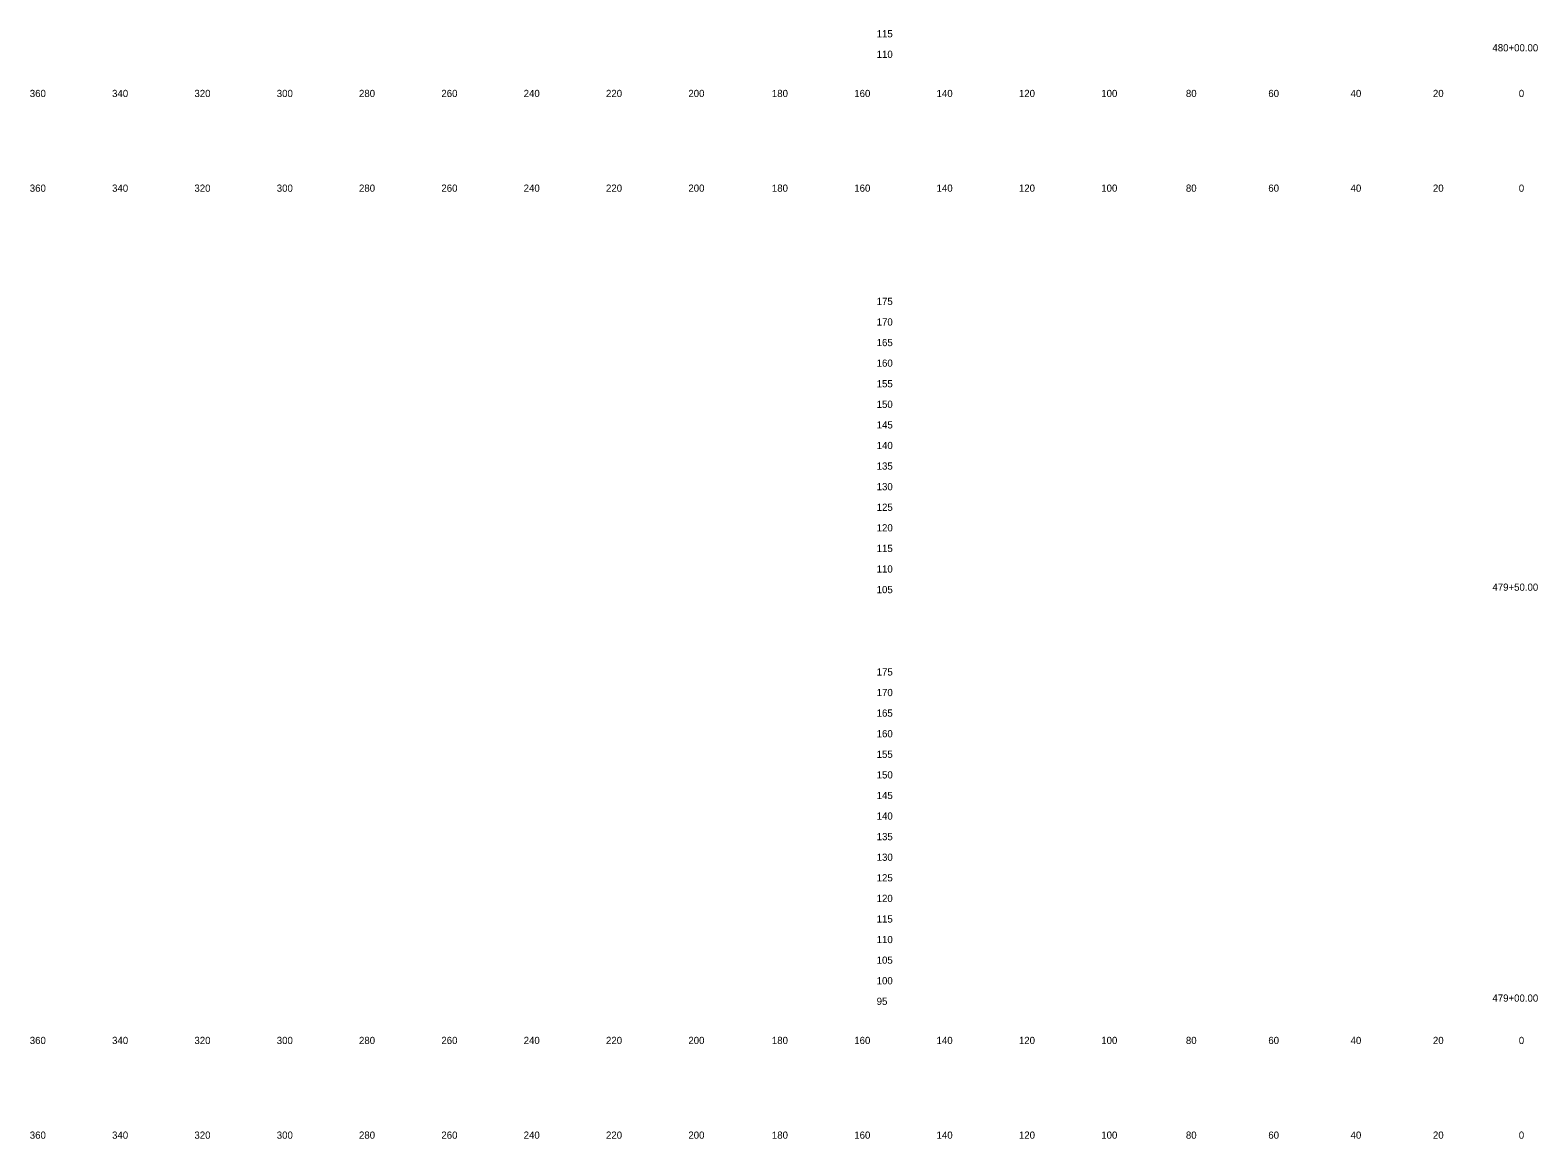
# Model space of a CAD drawing. Extents: x 21281 to 22024, y 6472 to 15198.
# Drawn here: x 21280.5 to 21646.7, y 12202.3 to 12471.6 of the extents above; entities that cross this region are included whole.
import ezdxf

# ---------------------------------------------------------------- set-up
doc = ezdxf.new("R2010")
doc.units = 0
for name, color, linetype in [('Draft_XS_Grid', 7, 'Continuous'), ('Draft_XS_Text', 7, 'Continuous'), ('SLOPE_STAKES_FILL', 7, 'Continuous')]:
    doc.layers.add(name, color=color, linetype=linetype)

msp = doc.modelspace()

# ---------------------------------------------------------------- texts
at = {"layer": 'Draft_XS_Grid'}
for s, p in [('  115  ', (21484.84, 12469.84)), ('  110  ', (21484.84, 12464.84)), ('  175  ', (21484.84, 12404.84)), ('  170  ', (21484.84, 12399.84)), ('  165  ', (21484.84, 12394.84)), ('  160  ', (21484.84, 12389.84)), ('  155  ', (21484.84, 12384.84)), ('  150  ', (21484.84, 12379.84)), ('  145  ', (21484.84, 12374.84)), ('  140  ', (21484.84, 12369.84)), ('  135  ', (21484.84, 12364.84)), ('  130  ', (21484.84, 12359.84)), ('  125  ', (21484.84, 12354.84)), ('  120  ', (21484.84, 12349.84)), ('  115  ', (21484.84, 12344.84)), ('  110  ', (21484.84, 12339.84)), ('  105  ', (21484.84, 12334.84)), ('  175  ', (21484.84, 12314.84)), ('  170  ', (21484.84, 12309.84)), ('  165  ', (21484.84, 12304.84)), ('  160  ', (21484.84, 12299.84)), ('  155  ', (21484.84, 12294.84)), ('  150  ', (21484.84, 12289.84)), ('  145  ', (21484.84, 12284.84)), ('  140  ', (21484.84, 12279.84)), ('  135  ', (21484.84, 12274.84)), ('  130  ', (21484.84, 12269.84)), ('  125  ', (21484.84, 12264.84)), ('  120  ', (21484.84, 12259.84)), ('  115  ', (21484.84, 12254.84)), ('  110  ', (21484.84, 12249.84)), ('  105  ', (21484.84, 12244.84)), ('  100  ', (21484.84, 12239.84)), ('  95  ', (21484.84, 12234.84))]:
    msp.add_text(s, height=1.75, dxfattribs=at).set_placement(p)
at = {"layer": 'Draft_XS_Text'}
for s, p in [('  360  ', (21279.14, 12455.34)), ('  340  ', (21299.13, 12455.34)), ('  320  ', (21319.13, 12455.34)), ('  300  ', (21339.13, 12455.34)), ('  280  ', (21359.1, 12455.34)), ('  260  ', (21379.11, 12455.34)), ('  240  ', (21399.1, 12455.34)), ('  220  ', (21419.1, 12455.34)), ('  200  ', (21439.1, 12455.34)), ('  180  ', (21459.39, 12455.34)), ('  160  ', (21479.4, 12455.34)), ('  140  ', (21499.39, 12455.34)), ('  120  ', (21519.39, 12455.34)), ('  100  ', (21539.39, 12455.34)), ('  80  ', (21559.95, 12455.34)), ('  60  ', (21579.97, 12455.34)), ('  40  ', (21599.95, 12455.34)), ('  20  ', (21619.95, 12455.34)), ('  0  ', (21640.81, 12455.34)), ('  0  ', (21640.81, 12455.34)), ('  360  ', (21279.14, 12432.34)), ('  340  ', (21299.13, 12432.34)), ('  320  ', (21319.13, 12432.34)), ('  300  ', (21339.13, 12432.34)), ('  280  ', (21359.1, 12432.34)), ('  260  ', (21379.11, 12432.34)), ('  240  ', (21399.1, 12432.34)), ('  220  ', (21419.1, 12432.34)), ('  200  ', (21439.1, 12432.34)), ('  180  ', (21459.39, 12432.34)), ('  160  ', (21479.4, 12432.34)), ('  140  ', (21499.39, 12432.34)), ('  120  ', (21519.39, 12432.34)), ('  100  ', (21539.39, 12432.34)), ('  80  ', (21559.95, 12432.34)), ('  60  ', (21579.97, 12432.34)), ('  40  ', (21599.95, 12432.34)), ('  20  ', (21619.95, 12432.34)), ('  0  ', (21640.81, 12432.34)), ('  0  ', (21640.81, 12432.34)), ('  360  ', (21279.14, 12225.34)), ('  340  ', (21299.13, 12225.34)), ('  320  ', (21319.13, 12225.34)), ('  300  ', (21339.13, 12225.34)), ('  280  ', (21359.1, 12225.34)), ('  260  ', (21379.11, 12225.34)), ('  240  ', (21399.1, 12225.34)), ('  220  ', (21419.1, 12225.34)), ('  200  ', (21439.1, 12225.34)), ('  180  ', (21459.39, 12225.34)), ('  160  ', (21479.4, 12225.34)), ('  140  ', (21499.39, 12225.34)), ('  120  ', (21519.39, 12225.34)), ('  100  ', (21539.39, 12225.34)), ('  80  ', (21559.95, 12225.34)), ('  60  ', (21579.97, 12225.34)), ('  40  ', (21599.95, 12225.34)), ('  20  ', (21619.95, 12225.34)), ('  0  ', (21640.81, 12225.34)), ('  0  ', (21640.81, 12225.34)), ('  360  ', (21279.14, 12202.34)), ('  340  ', (21299.13, 12202.34)), ('  320  ', (21319.13, 12202.34)), ('  300  ', (21339.13, 12202.34)), ('  280  ', (21359.1, 12202.34)), ('  260  ', (21379.11, 12202.34)), ('  240  ', (21399.1, 12202.34)), ('  220  ', (21419.1, 12202.34)), ('  200  ', (21439.1, 12202.34)), ('  180  ', (21459.39, 12202.34)), ('  160  ', (21479.4, 12202.34)), ('  140  ', (21499.39, 12202.34)), ('  120  ', (21519.39, 12202.34)), ('  100  ', (21539.39, 12202.34)), ('  80  ', (21559.95, 12202.34)), ('  60  ', (21579.97, 12202.34)), ('  40  ', (21599.95, 12202.34)), ('  20  ', (21619.95, 12202.34)), ('  0  ', (21640.81, 12202.34)), ('  0  ', (21640.81, 12202.34))]:
    msp.add_text(s, height=1.75, dxfattribs=at).set_placement(p)
at = {"layer": 'SLOPE_STAKES_FILL'}
for s, p in [('  480+00.00  ', (21634.4, 12466.44)), ('  479+50.00  ', (21634.4, 12335.43)), ('  479+00.00  ', (21634.4, 12235.63))]:
    msp.add_text(s, height=1.75, dxfattribs=at).set_placement(p)

doc.saveas('drawing.dxf')
